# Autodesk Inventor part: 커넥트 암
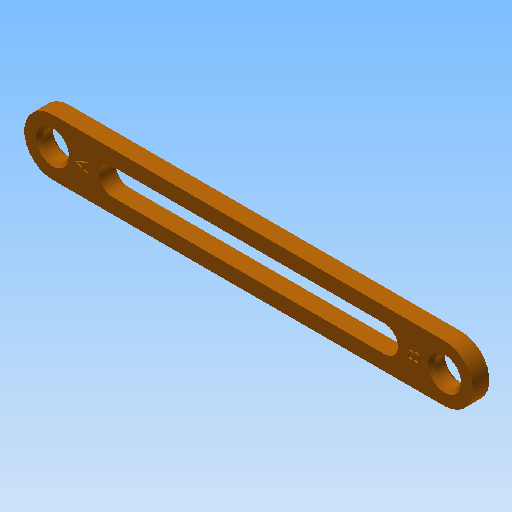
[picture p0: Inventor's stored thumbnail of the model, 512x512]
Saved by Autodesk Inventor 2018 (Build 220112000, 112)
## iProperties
Created: 2017-07
Part Number: 커넥트 암
Material: 스테인리스강
Document SubType Name: Modeling
Designer: mduedu
Density: 8.08 g/cm^3
Mass: 57.2031 g
Surface Area: 54.631 cm^2
Volume: 7.07959 cm^3
Appearance: 주황색
Author: mduedu
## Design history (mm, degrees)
sketch "스케치1"
  geometry: L1 (-67.5, 0)-(67.5, 0); L2 (-67.5, -8.5)-(67.5, -8.5); L3 (67.5, -8.5)-(67.5, 8.5); L4 (67.5, 8.5)-(-67.5, 8.5); L5 (-67.5, 8.5)-(-67.5, -8.5); L6 (-67.5, -8.5)-(67.5, 8.5); L7 (67.5, -8.5)-(-67.5, 8.5); 2 further points
  constraints: 14 end point, 4 midpoint, 2 horizontal, 2 parallel, 1 coincident, 1 perpendicular
  dimensions: "d0" = 135 distance of L1.start L1.end; "d2" = 17 distance of L2.end L3.end
extrude "돌출1" new body sketch "스케치1" distance "d3" = 5; taper "d4" = 0 deg
fillet "모깎기1"
fillet "모깎기2"
sketch "스케치2"
  geometry: C1 r 4 at (59, 0); A1 r 8.5 centre (59, 0) between (59, -8.5) and (59, 8.5) reference; 1 further point
  constraints: 1 centre point, 1 coincident
  dimensions: "d5" = 8 diameter of C1
extrude "돌출2" cut sketch "스케치2" extent not by distance; stored distance "d6" = 10; taper "d7" = 0 deg
chamfer "모따기1" distance "d8" = 1; stored, may be unused: second distance "d9" = 2, angle "d10" = 45 deg
sketch "스케치3"
  geometry: L1 (-45, 0)-(45, 0); L2 (-45, -4)-(45, -4); L3 (45, -4)-(45, 4); L4 (45, 4)-(-45, 4); L5 (-45, 4)-(-45, -4); L6 (-45, -4)-(45, 4); L7 (45, -4)-(-45, 4); 2 further points
  constraints: 14 end point, 4 midpoint, 2 horizontal, 2 parallel, 1 coincident, 1 perpendicular
  dimensions: "d11" = 90 distance of L1.start L1.end; "d13" = 8 distance of L2.end L3.end
extrude "돌출3" cut sketch "스케치3" extent not by distance; stored distance "d14" = 10; taper "d15" = 0 deg
fillet "모깎기3"
fillet "모깎기4"
sketch "스케치4"
  geometry: L1 (-59, 0)-(59, 0); C1 r 5 at (-59, 0) reference; C2 r 5 at (59, 0) reference; 3 further points
  constraints: 2 end point, 2 point on line, 1 horizontal, 2 other
  dimensions: "d16" = 50 distance of point (-50, 0) point (0, 0); "d17" = 50 distance of point (50, 0) point (0, 0)
feature "엠보싱1" sketch "스케치4" dims "d0" = 135, "d2" = 17, "d18" = 0.5, "d19" = 0
node "솔리드1"
mirror "대칭1"
